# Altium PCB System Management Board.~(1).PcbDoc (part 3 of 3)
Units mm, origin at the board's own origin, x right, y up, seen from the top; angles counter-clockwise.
Board outline 150 x 110 mm, 4 copper layers (F.Cu, In1.Cu, In2.Cu, B.Cu); 151 components, 121 nets, 513 pads, 536 vias.
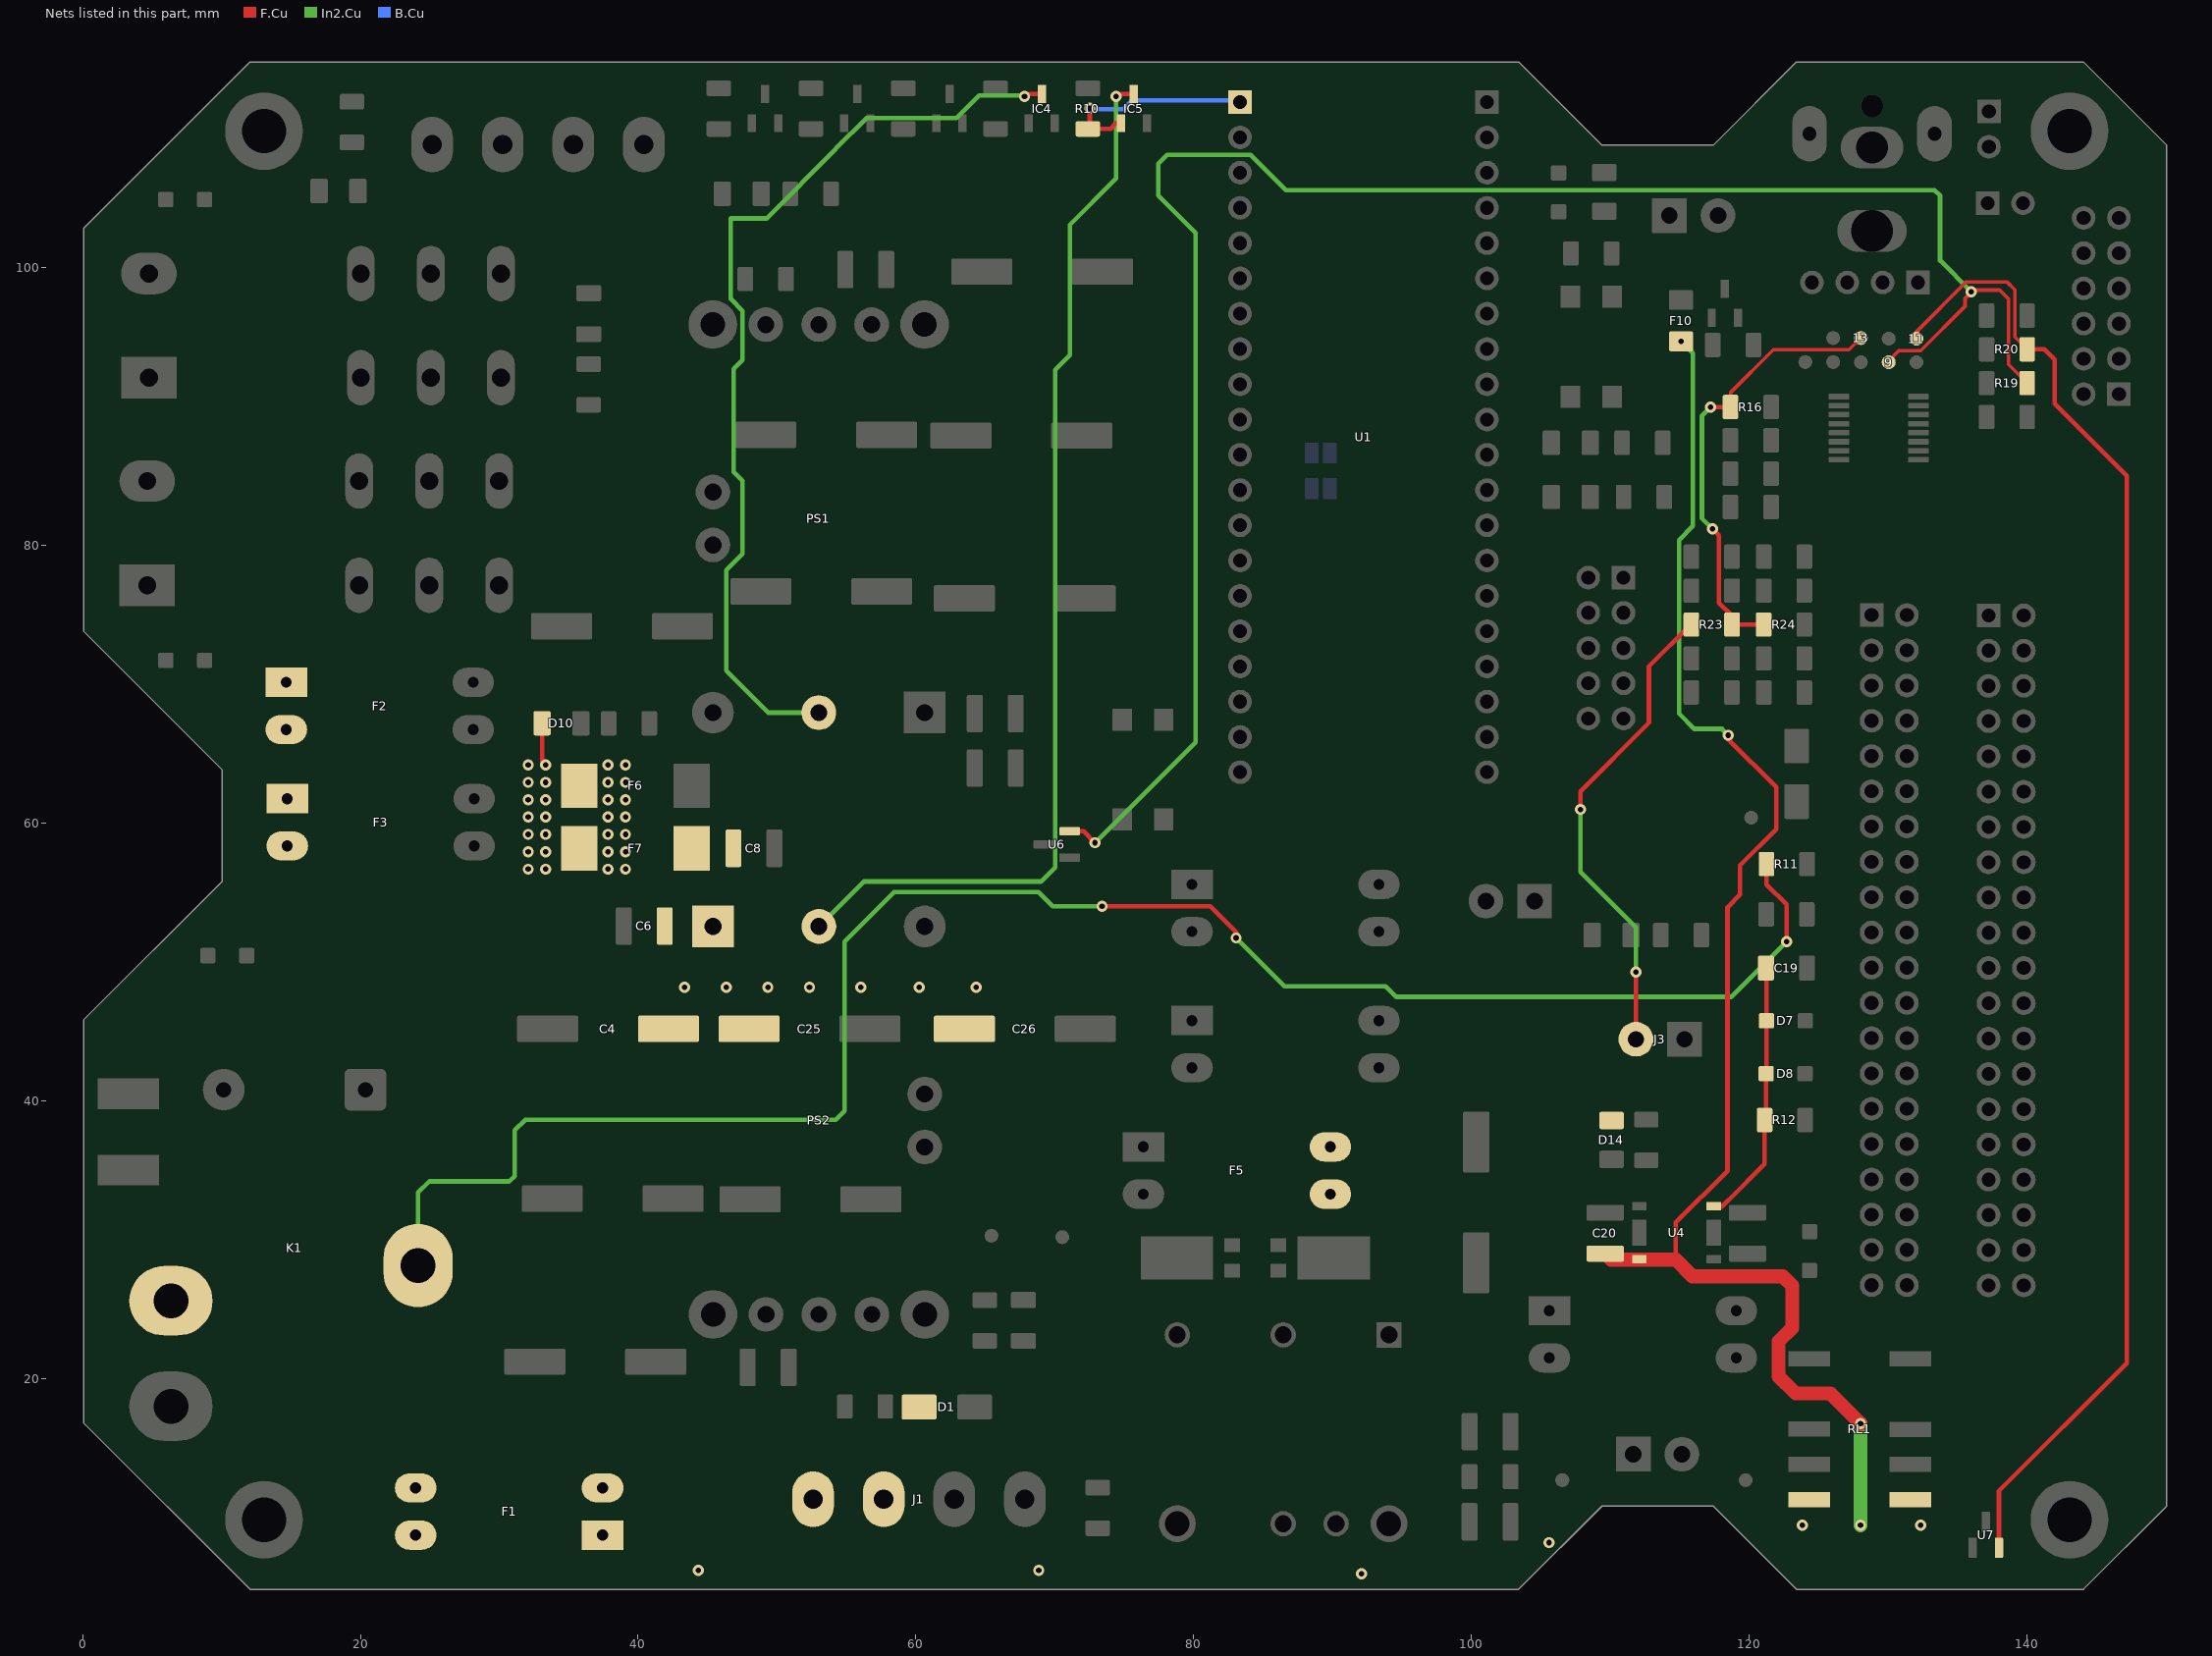
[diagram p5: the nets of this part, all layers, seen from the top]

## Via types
v1: diameter 0.8, hole 0.4, F.Cu to B.Cu, tented both sides, 536 vias

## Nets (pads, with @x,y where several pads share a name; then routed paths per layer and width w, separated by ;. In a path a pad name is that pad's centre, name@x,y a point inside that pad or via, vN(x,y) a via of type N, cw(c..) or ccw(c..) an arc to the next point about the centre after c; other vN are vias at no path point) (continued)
"POE_SW_Vout MES_ADC": 13.1 R16.1 R23.1 R24.1 | length 31.9
  F.Cu w0.25: R16.1@118.649,89.967 118.649,90.995 121.74,94.087 127.19,94.087 13.1@128.04,94.937
  F.Cu w0.33: v1(117.221,89.956) R16.1@118.638,89.956 ; v1(117.348,81.193) 117.819,80.722 117.819,75.87 R23.1@118.757,74.932 ; R23.1@118.756,74.299 R24.1@121.044,74.299
  In2.Cu w0.33: v1(117.221,89.956) 116.59,89.325 116.59,81.951 v1(117.348,81.193)
PSPS_IN_PROT: C4.1 C6.1 C8.1 C25.1 C26.1 F7.2 PS2.1
  other v1: 43.34,48.187 46.34,48.187 49.34,48.187 52.34,48.187 56.04,48.187 60.24,48.187 64.34,48.187
"SWITCH PWR EN": IC5.1 R10.1 U1.1 | length 15.1
  F.Cu w0.33: R10.1@72.378,109.994 74.014,109.994 74.426,110.407 IC5.1@74.75,110.407 ; R10.1@72.517,110.133 v1(72.517,111.486)
  B.Cu w0.33: v1(72.517,111.486) 72.585,111.419 74.93,111.419 75.565,112.054 83.213,112.054 U1.1@83.34,111.927
"SWITCH PWR OUT PROT": D14.2 F5.3 F5.4 J3.2 R23.2 | length 34.8
  F.Cu w0.33: v1(107.84,60.987) 107.84,62.287 112.776,67.223 112.776,71.287 R23.2@115.788,74.299 ; J3.2@111.84,44.437 v1(111.84,49.287)
  In2.Cu w0.33: v1(107.84,60.987) 107.84,56.487 111.84,52.487 v1(111.84,49.287)
"Switched PWR IN PROT": C19.1 D7.1 D8.1 R12.2 U4.3 | length 19
  F.Cu w0.33: U4.3@117.377,32.377 118.03,32.377 118.162,32.509 118.162,32.533 118.516,32.887 118.54,32.887 121.106,35.452 R12.2@121.106,38.623 ; R12.2@121.217,38.734 D8.1@121.217,41.96 ; D8.1@121.236,41.979 D7.1@121.236,45.77 C19.1@121.236,49.541
TEMP_SENSE_1: 9.1 R19.1 U6.2 | length 138.8
  F.Cu w0.25: 9.1@130.04,93.287 130.765,94.012 132.332,94.012 135.54,97.22 135.54,97.787 136.14,98.387 138.04,98.387 138.674,97.753 138.674,93.022 R19.1@140.011,91.685
  F.Cu w0.33: U6.2@71.069,59.418 72.067,59.418 v1(72.898,58.587)
  In2.Cu w0.33: v1(72.898,58.587) 80.137,65.826 80.137,102.49 77.44,105.187 77.44,107.487 78.077,108.124 84.103,108.124 86.64,105.587 133.34,105.587 133.74,105.187 133.74,100.513 v1(135.991,98.263)
TEMP_SENSE_2: 11.1 R20.1 U7.2 | length 107.8
  F.Cu w0.25: 11.1@132.04,94.887 132.04,95.387 135.64,98.987 138.54,98.987 139.124,98.403 139.124,95.006 R20.1@140.011,94.118
  F.Cu w0.33: U7.2@137.979,7.815 137.979,11.908 147.193,21.122 147.193,85.003 141.986,90.21 141.986,93.385 141.252,94.118 R20.1@140.011,94.118
V_batt+: D1.2 F1.1 F1.2 J1.3 J1.4
"V_batt+ PROT": C20.1 F1.3 F1.4 F10.1 K1.14 RL1.NO1 RL1.NO2 U4.6 | length 110
  F.Cu w0.33: 114.71,28.567 114.71,31.249 118.437,34.976 118.437,53.95 119.34,54.853 119.34,56.963 121.94,59.563 121.94,62.587 118.491,66.036 v1(118.491,66.334)
  F.Cu w1: C20.1@109.627,28.997 110.057,28.567 112.028,28.567 114.71,28.567 115.91,27.367 122.41,27.367 123.09,26.687 123.09,23.655 122.12,22.685 122.12,20.157 123.34,18.937 125.84,18.937 v1(128.016,16.761) ; RL1.NO2@131.592,11.275 RL1.NO2@131.597,11.27
  In2.Cu w0.33: v1(115.09,94.699) 115.951,93.838 115.951,81.398 114.94,80.387 114.94,67.887 116.04,66.787 118.038,66.787 v1(118.491,66.334)
  In2.Cu w1: v1(128.016,9.438) v1(128.016,16.761)
  other v1: 92.09,5.937 44.34,6.187 68.84,6.187 105.59,8.187 123.825,9.438 132.334,9.438
"V_batt+ PROT SW": D10.2 F2.1 F2.2 F3.1 F3.2 F6.1 F7.1 K1.11 R11.1 | length 136.1
  F.Cu w0.33: D10.2@33.084,67.187 33.084,64.443 v1(33.34,64.187) ; v1(73.406,54.015) 81.189,54.015 83.058,52.146 v1(83.058,51.729) ; R11.1@121.241,57.051 121.241,55.582 122.682,54.142 v1(122.682,51.475)
  In2.Cu w0.33: K1.11@24.16,28.147 24.16,33.407 24.956,34.203 30.734,34.203 31.115,34.584 31.115,37.886 31.877,38.648 54.229,38.648 54.864,39.283 54.864,51.475 58.42,55.031 68.834,55.031 69.85,54.015 v1(73.406,54.015) ; v1(83.058,51.729) 86.53,48.256 93.82,48.256 94.59,47.487 118.694,47.487 v1(122.682,51.475)
  other v1: 32.09,56.687 33.34,56.687 37.84,56.687 39.09,56.687 32.09,57.937 33.34,57.937 37.84,57.937 39.09,57.937 32.09,59.187 33.34,59.187 37.84,59.187 39.09,59.187 32.09,60.437 33.34,60.437 37.84,60.437 39.09,60.437 32.09,61.687 33.34,61.687 37.84,61.687 39.09,61.687 32.09,62.937 33.34,62.937 37.84,62.937 39.09,62.937 32.09,64.187 37.84,64.187 39.09,64.187
"{\C\O\M\P\ \P\W\R\ \E\N\}\": IC4.3 PS1.2 | length 68.1
  F.Cu w0.33: v1(67.818,112.332) 67.993,112.507 IC4.3@69.057,112.507
  In2.Cu w0.33: PS1.2@53.005,67.962 49.35,67.962 46.34,70.971 46.34,78.211 47.523,79.394 47.523,84.642 46.886,85.279 46.886,92.726 47.523,93.363 47.523,96.89 46.66,97.753 46.66,103.545 49.242,103.545 54.24,108.543 54.24,108.577 56.444,110.781 62.917,110.781 64.543,112.407 67.743,112.407 v1(67.818,112.332)
"{\S\W\I\T\C\H\ \P\W\R\ \E\N\}\": IC5.3 PS2.2 | length 77.5
  F.Cu w0.33: v1(74.422,112.332) 74.597,112.507 IC5.3@75.7,112.507
  In2.Cu w0.33: PS2.2@53.015,52.562 56.246,55.793 69.012,55.793 70.028,56.809 70.028,92.648 71.095,93.715 71.095,103.087 74.422,106.415 v1(74.422,112.332)
pads on no net: J4.Un1 J6.2 J6.3 J6.7 J6.8 J6.11 K2.12 K3.12 PS1.5 PS2.5 RL1.NC1 RL1.NC2 U1.35 U1.37 U1.40

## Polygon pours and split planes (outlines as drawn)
V_batt+ on F.Cu "F.Cu-/V_batt+" (solid, remove dead copper, pour order 41): 60.321,7.747 31.34,7.747 31.34,17.187 60.34,17.187
GND on F.Cu "F.Cu-GND-1" (solid, remove dead copper, pour order 73): 151.13,2.707 -2.54,2.707 -2.54,115.737 151.13,115.737
"48V PWR" on F.Cu "F.Cu-/48V PWR" (solid, remove dead copper, pour order 32): 52.59,27.437 49.34,22.437 49.365,17.437 37.09,17.437 37.09,27.687 38.09,29.187 38.09,38.687 52.59,38.687
"V_batt+ PROT" on F.Cu "F.Cu-/V_batt+ PROT-1" (solid, remove dead copper, pour order 33): 14.34,21.687 18.84,17.187 31.34,17.187 31.34,4.687 11.84,4.687 -0.16,17.187 0,29.123 14.34,29.123
"LIGHT BANK B PROT SW" on F.Cu "F.Cu-/LIGHT BANK B PROT SW" (solid, remove dead copper, pour order 34): 32.79,108.862 32.84,90.687 31.84,89.687 27.59,89.687 27.59,112.187 32.84,112.187
"LIGHT BANK B PROT" on F.Cu "F.Cu-/LIGHT BANK B PROT" (solid, remove dead copper, pour order 35): 27.34,89.687 24.59,89.687 22.34,87.687 22.352,74.081 24.59,71.541 24.59,66.437 26.59,64.187 30.34,64.187 30.34,56.437 26.162,56.529 19.09,63.687 19.09,70.687 16.34,73.937 16.34,92.687 22.34,99.187 22.34,102.687 27.34,102.687
"V_batt+ PROT SW" on F.Cu "F.Cu-/V_batt+ PROT SW" (solid, remove dead copper, pour order 42): 18.84,70.687 18.84,63.687 26.162,56.224 28.84,56.187 30.59,57.937 30.59,63.937 32.34,65.687 39.84,65.687 39.84,55.937 33.44,55.937 27.34,49.687 27.34,26.837 25.34,24.043 14.59,24.043 14.59,37.251 10.59,40.807 10.59,73.687 16.34,73.687
"LIGHT BANK A PROT" on F.Cu "F.Cu-/LIGHT BANK A PROT" (solid, remove dead copper, pour order 43): 27.686,76.113 30.34,73.319 30.34,64.437 26.59,64.437 24.84,66.437 24.84,71.795 22.59,74.335 22.59,87.687 24.59,89.437 27.34,89.437
"15v PWR" on F.Cu "F.Cu-/15v PWR" (solid, remove dead copper, pour order 48): 53.34,92.687 56.565,98.587 56.54,103.587 68.815,103.587 68.815,91.734 67.818,91.734 67.815,82.337 53.315,82.337
"LIGHT BANK A PROT SW" on F.Cu "F.Cu-/LIGHT BANK A PROT SW" (solid, remove dead copper, pour order 49): 43.09,107.687 38.34,102.937 38.34,88.387 34.74,84.987 34.09,84.187 34.09,81.387 33.54,80.787 33.54,75.587 32.84,74.587 29.21,74.589 27.686,76.113 27.59,89.437 31.84,89.437 33.09,90.687 33.09,104.187 37.84,108.937 37.84,112.187 43.09,112.187
PSPS_IN_PROT on F.Cu "F.Cu-/PSPS_IN_PROT" (solid, remove dead copper, pour order 52): 48.34,60.187 42.24,60.187 42.24,56.437 40.24,54.537 40.24,49.037 39.34,47.187 39.34,43.387 51.24,43.387 51.24,46.587 59.54,46.587 59.54,43.387 66.34,43.387 66.34,50.437 50.84,50.437 48.34,56.437
CPS_IN_PROT on F.Cu "F.Cu-/CPS_IN_PROT" (solid, remove dead copper, pour order 55): 42.09,60.687 65.84,60.687 65.84,79.187 53.84,79.187 53.84,77.287 52.34,75.437 40.34,75.387 40.34,72.387 52.34,72.387 55.84,69.437 55.84,64.987 42.09,64.987
"V_batt+ PROT" on F.Cu "F.Cu-/V_batt+ PROT" (solid, remove dead copper, pour order 60): 133.59,12.437 107.84,12.437 102.84,7.437 33.34,7.437 30.34,10.187 30.34,4.687 103.59,4.687 109.59,10.687 117.34,10.687 123.34,4.687 133.59,4.437
"5V Intermediate" on F.Cu "F.Cu-/5V Intermediate" (solid, remove dead copper, pour order 61): 81.84,30.687 87.09,30.687 87.09,26.187 95.84,18.687 100.59,18.687 101.34,17.937 101.34,8.687 100.59,7.937 89.84,7.937 88.59,9.187 88.59,14.187 81.84,20.937
i3_Vin on F.Cu "F.Cu-/i3_Vin" (solid, remove dead copper, pour order 62): 133.59,15.187 123.09,15.187 117.34,19.687 105.09,19.687 102.34,22.187 102.34,30.937 98.09,30.937 92.84,26.187 89.84,26.187 89.84,23.937 95.84,18.687 100.59,18.687 101.34,17.937 105.09,16.687 116.34,16.687 121.59,12.437 133.59,12.437
"15V Aux PWR OUT PROT" on F.Cu "F.Cu-/15V Aux PWR OUT PROT" (solid, remove dead copper, pour order 66): 96.59,42.687 96.593,46.205 102.74,51.587 102.74,56.987 98.54,56.987 98.54,53.887 90.74,47.387 90.74,40.687 94.09,40.687
"SWITCH PWR OUT PROT" on F.Cu "F.Cu-/SWITCH PWR OUT PROT" (solid, remove dead copper, pour order 67): 87.09,31.187 87.09,39.437 89.34,40.687 94.09,40.687 96.59,42.687 107.24,42.687 110.24,46.737 113.84,46.737 113.84,42.687 111.34,39.437 111.34,37.687 108.84,37.687 106.84,39.287 97.59,39.437 94.09,36.437 94.09,33.937 94.09,31.937 93.09,31.187
GND on F.Cu "F.Cu-GND" (solid, remove dead copper, pour order 69): 82.94,4.887 60.315,4.687 60.34,17.187 82.94,17.387
"COMP PWR OUT PROT" on F.Cu "F.Cu-/COMP PWR OUT PROT" (solid, remove dead copper, pour order 70): 98.54,53.887 98.54,56.987 106.84,56.987 107.64,55.887 107.64,50.887 110.04,50.787 110.04,59.887 91.14,59.887 91.14,50.387 94.34,50.387
"48V PWR" on In2.Cu "In2.Cu-/48V PWR-1" (solid, remove dead copper, pour order 57): 51.59,31.437 71.09,31.437 73.09,33.187 73.09,38.937 80.09,38.937 80.09,35.187 84.34,31.187 104.59,31.187 107.59,28.187 107.59,19.687 102.34,19.687 102.34,26.187 61.84,26.187 59.59,26.187 51.59,26.187
"48V Aux PWR OUT PROT" on In2.Cu "In2.Cu-/48V Aux PWR OUT PROT" (solid, remove dead copper, pour order 64): 113.34,12.687 113.34,16.437 113.34,20.187 113.34,26.437 122.09,26.437 122.09,23.937 121.34,23.187 121.34,12.687 117.84,12.687
GND on In2.Cu "In2.Cu-GND-3" (solid, remove dead copper, pour order 47): 0,29.377 0,45.887 3.81,49.697 10.668,49.697 20.066,40.553 20.066,29.377
GND on In2.Cu "In2.Cu-GND-2" (solid, remove dead copper, pour order 23): 77.216,114.975 77.216,59.857 106.68,59.857 106.68,114.975
PSPS_IN_PROT on In2.Cu "In2.Cu-/PSPS_IN_PROT" (solid, remove dead copper, pour order 51): 48.34,60.187 42.24,60.187 42.24,56.437 40.24,54.537 40.24,49.037 39.34,47.187 39.34,43.387 51.24,43.387 51.24,46.587 59.54,46.587 59.54,43.387 66.34,43.387 66.34,50.437 50.84,50.437 48.34,56.437
"V_batt+ PROT" on In2.Cu "In2.Cu-/V_batt+ PROT-1" (solid, remove dead copper, pour order 31): 14.34,21.687 18.84,17.187 31.34,17.187 31.34,4.687 11.84,4.687 -0.16,17.187 0,29.123 14.34,29.123
CPS_IN_PROT on In2.Cu "In2.Cu-/CPS_IN_PROT" (solid, remove dead copper, pour order 54): 42.09,60.687 65.84,60.687 65.84,79.187 53.84,79.187 53.84,77.287 52.34,75.437 40.34,75.387 40.34,72.387 52.34,72.387 55.84,69.437 55.84,64.987 42.09,64.987
"V_batt+ PROT SW" on In2.Cu "In2.Cu-/V_batt+ PROT SW" (solid, remove dead copper, pour order 40): 18.84,70.687 18.84,63.687 26.162,56.224 28.84,56.187 30.59,57.937 30.59,63.937 32.34,65.687 39.84,65.687 39.84,55.937 33.44,55.937 27.34,49.687 27.34,26.837 25.34,24.043 14.59,24.043 14.59,37.251 10.59,40.807 10.59,73.687 16.34,73.687
"V_batt+ PROT" on In2.Cu "In2.Cu-/V_batt+ PROT" (solid, remove dead copper, pour order 59): 133.59,12.437 107.84,12.437 102.84,7.437 33.34,7.437 30.34,10.187 30.34,4.687 103.59,4.687 109.59,10.687 117.34,10.687 123.34,4.687 133.59,4.437
V_batt+ on In2.Cu "In2.Cu-/V_batt+" (solid, remove dead copper, pour order 39): 60.315,4.687 31.34,4.687 31.34,17.187 60.34,17.187
"48V PWR" on In2.Cu "In2.Cu-/48V PWR" (solid, remove dead copper, pour order 30): 52.59,27.437 49.34,22.437 49.365,17.437 37.09,17.437 37.09,27.687 38.09,29.187 38.09,38.687 52.59,38.687
GND on In2.Cu "In2.Cu-GND-1" (solid, remove dead copper, pour order 74): 151.13,2.707 -2.54,2.707 -2.54,115.737 151.13,115.737
"15v PWR" on In2.Cu "In2.Cu-/15v PWR" (solid, remove dead copper, pour order 46): 53.34,92.687 56.565,98.587 56.54,103.587 68.815,103.587 68.815,91.734 67.818,91.734 67.815,82.337 53.315,82.337
GND on In2.Cu "In2.Cu-GND" (solid, remove dead copper, pour order 71): 82.94,4.887 60.315,4.687 60.34,17.187 82.94,17.387
V_batt+ on B.Cu "B.Cu-/V_batt+" (solid, remove dead copper, pour order 36): 60.315,4.687 31.34,4.687 31.34,17.187 60.34,17.187
GND on B.Cu "B.Cu-GND-1" (solid, remove dead copper, pour order 77): 153.416,0 -6.223,0 -6.223,118.491 153.416,118.491
"15v PWR" on B.Cu "B.Cu-/15v PWR-1" (solid, remove dead copper, pour order 29): 81.872,41.288 80.54,40.045 75.692,40.045 74.549,41.315 74.549,80.685 72.898,82.336 67.437,82.336 67.437,91.861 76.708,91.861 81.872,87.77
"COMP PWR OUT PROT" on B.Cu "B.Cu-/COMP PWR OUT PROT-1" (solid, remove dead copper, pour order 28): 133.83,98.878 126.619,98.878 123.063,98.846 112.522,98.846 105.537,92.115 105.537,57.547 102.108,57.547 102.108,94.147 110.744,102.402 122.555,102.402 125.73,105.644 133.83,105.684
"48V PWR" on B.Cu "B.Cu-/48V PWR-1" (solid, remove dead copper, pour order 56): 51.59,31.437 71.09,31.437 73.09,33.187 73.09,38.937 80.09,38.937 80.09,35.187 84.34,31.187 104.59,31.187 107.59,28.187 107.59,19.687 102.34,19.687 102.34,26.187 61.84,26.187 59.59,26.187 51.59,26.187
"48V Aux PWR OUT PROT" on B.Cu "B.Cu-/48V Aux PWR OUT PROT" (solid, remove dead copper, pour order 63): 113.34,12.687 113.34,16.437 113.34,20.187 113.34,26.437 122.09,26.437 122.09,23.937 121.34,23.187 121.34,12.687 117.84,12.687
GND on B.Cu "B.Cu-GND-2" (solid, remove dead copper, pour order 22): 77.216,114.975 77.216,59.857 101.346,59.944 101.346,114.975
"LIGHT BANK B PROT" on B.Cu "B.Cu-/LIGHT BANK B PROT" (solid, remove dead copper, pour order 27): 27.34,89.687 24.59,89.687 22.34,87.687 22.352,74.081 24.59,71.541 24.59,66.437 26.59,64.187 30.34,64.187 30.34,56.437 26.162,56.529 19.09,63.687 19.09,70.687 16.34,73.937 16.34,92.687 22.34,99.187 22.34,102.687 27.34,102.687
"COMP PWR OUT PROT" on B.Cu "B.Cu-/COMP PWR OUT PROT" (solid, remove dead copper, pour order 68): 98.54,53.887 98.54,56.987 106.84,56.987 107.64,55.887 107.64,50.887 110.04,50.787 110.04,59.887 91.14,59.887 91.14,50.387 94.34,50.387
"LIGHT BANK B PROT SW" on B.Cu "B.Cu-/LIGHT BANK B PROT SW" (solid, remove dead copper, pour order 26): 32.79,108.862 32.84,90.687 31.84,89.687 27.59,89.687 27.59,112.187 32.84,112.187
"LIGHT BANK A PROT SW" on B.Cu "B.Cu-/LIGHT BANK A PROT SW" (solid, remove dead copper, pour order 45): 43.09,107.687 38.34,102.937 38.34,88.387 34.74,84.987 34.09,84.187 34.09,81.387 33.54,80.787 33.54,75.587 32.84,74.587 29.21,74.589 27.686,76.113 27.59,89.437 31.84,89.437 33.09,90.687 33.09,104.187 37.84,108.937 37.84,112.187 43.09,112.187
"LIGHT BANK A PROT" on B.Cu "B.Cu-/LIGHT BANK A PROT" (solid, remove dead copper, pour order 38): 27.686,76.113 30.34,73.319 30.34,64.437 26.59,64.437 24.84,66.437 24.84,71.795 22.59,74.335 22.59,87.687 24.59,89.437 27.34,89.437
"15V Aux PWR OUT PROT" on B.Cu "B.Cu-/15V Aux PWR OUT PROT" (solid, remove dead copper, pour order 65): 96.59,42.687 96.593,46.205 102.74,51.587 102.74,56.987 98.54,56.987 98.54,53.887 90.74,47.387 90.74,40.687 94.09,40.687
PSPS_IN_PROT on B.Cu "B.Cu-/PSPS_IN_PROT" (solid, remove dead copper, pour order 50): 48.34,60.187 42.24,60.187 42.24,56.437 40.24,54.537 40.24,49.037 39.34,47.187 39.34,43.387 51.24,43.387 51.24,46.587 59.54,46.587 59.54,43.387 66.34,43.387 66.34,50.437 50.84,50.437 48.34,56.437
"V_batt+ PROT" on B.Cu "B.Cu-/V_batt+ PROT-1" (solid, remove dead copper, pour order 25): 14.34,21.687 18.84,17.187 31.34,17.187 31.34,4.687 11.84,4.687 -0.16,17.187 0,29.123 14.34,29.123
CPS_IN_PROT on B.Cu "B.Cu-/CPS_IN_PROT" (solid, remove dead copper, pour order 53): 42.09,60.687 65.84,60.687 65.84,79.187 53.84,79.187 53.84,77.287 52.34,75.437 40.34,75.387 40.34,72.387 52.34,72.387 55.84,69.437 55.84,64.987 42.09,64.987
"V_batt+ PROT SW" on B.Cu "B.Cu-/V_batt+ PROT SW" (solid, remove dead copper, pour order 37): 18.84,70.687 18.84,63.687 26.162,56.224 28.84,56.187 30.59,57.937 30.59,63.937 32.34,65.687 39.84,65.687 39.84,55.937 33.44,55.937 27.34,49.687 27.34,26.837 25.34,24.043 14.59,24.043 14.59,37.251 10.59,40.807 10.59,73.687 16.34,73.687
"V_batt+ PROT" on B.Cu "B.Cu-/V_batt+ PROT" (solid, remove dead copper, pour order 58): 133.59,12.437 107.84,12.437 102.84,7.437 33.34,7.437 30.34,10.187 30.34,4.687 103.59,4.687 109.59,10.687 117.34,10.687 123.34,4.687 133.59,4.437
"48V PWR" on B.Cu "B.Cu-/48V PWR" (solid, remove dead copper, pour order 24): 52.59,27.437 49.34,22.437 49.365,17.437 37.09,17.437 37.09,27.687 38.09,29.187 38.09,38.687 52.59,38.687
"15v PWR" on B.Cu "B.Cu-/15v PWR" (solid, remove dead copper, pour order 44): 53.34,92.687 56.565,98.587 56.54,103.587 68.815,103.587 68.815,91.734 67.818,91.734 67.815,82.337 53.315,82.337
GND on B.Cu "B.Cu-GND" (solid, remove dead copper, pour order 72): 82.94,4.887 60.315,4.687 60.34,17.187 82.94,17.387
GND on In1.Cu "In1.Cu-GND-1" (solid, remove dead copper, pour order 21): 77.216,114.975 77.216,59.857 106.68,59.857 106.68,114.975
GND on In1.Cu "In1.Cu-GND" (solid, remove dead copper, pour order 76): 151.13,2.707 -2.54,2.707 -2.54,115.737 151.13,115.737

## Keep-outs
F.Cu:
  region: 148.209,89.194 142.367,89.194 142.367,105.323 148.209,105.323
  region: 141.986,75.478 141.986,25.948 140.589,24.551 127.762,24.551 126.492,25.948 126.492,75.605 127.508,76.875 140.843,76.875
  region: 112.649,65.826 106.807,65.826 106.807,79.415 112.649,79.415
  region: 149.225,4.358 133.723,4.358 133.723,12.232 139.827,12.232
In1.Cu:
  region: 149.225,4.358 133.723,4.358 133.723,12.232 139.827,12.232
In2.Cu:
  region: 148.209,89.194 142.367,89.194 142.367,105.323 148.209,105.323
  region: 141.986,75.478 141.986,25.948 140.589,24.551 127.762,24.551 126.492,25.948 126.492,75.605 127.508,76.875 140.843,76.875
  region: 112.649,65.826 106.807,65.826 106.807,79.415 112.649,79.415
  region: 149.225,4.358 133.723,4.358 133.723,12.232 139.827,12.232
B.Cu:
  region: 148.209,89.194 142.367,89.194 142.367,105.323 148.209,105.323
  region: 141.986,75.478 141.986,25.948 140.589,24.551 127.762,24.551 126.492,25.948 126.492,75.605 127.508,76.875 140.843,76.875
  region: 112.649,65.826 106.807,65.826 106.807,79.415 112.649,79.415
  region: 149.225,4.358 133.723,4.358 133.723,12.232 139.827,12.232
Edge.Cuts:
  circle w0.254: c113.398,59.821 r5
  lines w0: 0.065,16.821 12.065,4.821 103.398,4.821 109.398,10.821 117.398,10.821 123.398,4.821 144.065,4.821 150.065,10.821 150.065,108.821 144.065,114.821 123.398,114.821 117.398,108.821 109.398,108.821 103.398,114.821 12.065,114.821 0.065,102.821 0.065,73.821 10.065,63.821 10.065,55.821 0.065,45.821 0.065,16.821
  lines w0.254: 0.065,16.821 12.065,4.821 103.398,4.821 109.398,10.821 117.398,10.821 123.398,4.821 144.065,4.821 150.065,10.821 150.065,108.821 144.065,114.821 123.398,114.821 117.398,108.821 109.398,108.821 103.398,114.821 12.065,114.821 0.065,102.821 0.065,73.821 10.065,63.821 10.065,55.821 0.065,45.821 0.065,16.821

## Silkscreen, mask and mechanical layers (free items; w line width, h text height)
F.SilkS:
  text "14" at 125.44,95.507 h1
  text "13" at 127.34,95.502 h1
  text "12" at 129.34,95.507 h1
  text "11" at 131.34,95.51 h1
  text "TP:" at 123.249,94.206 h1
  text "RESET" at 113.585,91.51 h1.5
  text "6" at 123.64,90.805 h1
  text "7" at 125.64,90.805 h1
  text "8" at 127.64,90.802 h1
  text "9" at 129.84,90.807 h1
  text "10" at 131.34,90.802 h1
  text "lantMap" at 48.611,61.046 h2.5
  text "P" at 45.14,59.077 h4
  text "AUX SW" at 89.616,58.517 h2
  text "V0.3" at 62.74,55.202 h1
  text "3D" at 55.14,55.046 h4
B.SilkS:
  text "lantMap" at 132.34,88.058 h3
  text "P" at 136.658,86.041 h5
  text "3D" at 116.211,85.845 h5
  text "System Management Board V0.3 / 7-30-2024 -- M. Funderburk, C. Nichols / Precision Sustainable Agriculture" at 136.023,83.454 h1

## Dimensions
0.065,16.821 to 150.114,16.804 on Eco1.User
144.065,114.821 to 143.99,75.312 on Eco1.User
144.065,114.821 to 144.065,4.821 on Eco1.User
